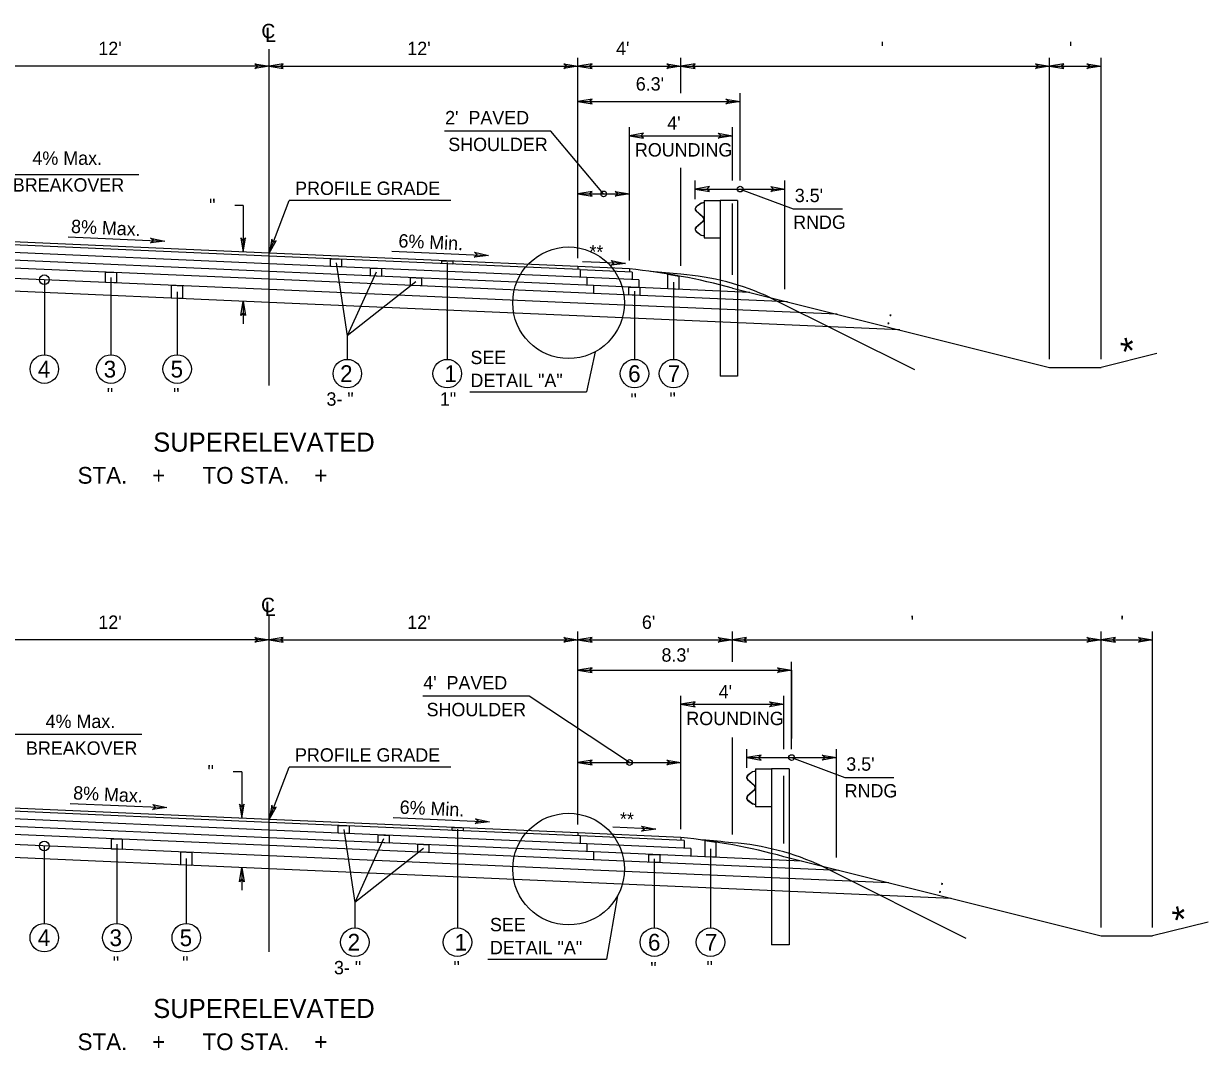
# Model space of a CAD drawing. Extents: x -592 to 1199, y -590 to 416.
# Drawn here: x 1064.4 to 1188.4, y -214.2 to -106.8 of the extents above; entities that cross this region are included whole.
import ezdxf

# ---------------------------------------------------------------- set-up
doc = ezdxf.new("R2010")
doc.units = 0
doc.layers.add('1', color=7, linetype='Continuous')
doc.layers.add('Des_ Drain_ Ftrs', color=7, linetype='Continuous')

msp = doc.modelspace()

# ---------------------------------------------------------------- linework, layer by layer
at = {"layer": '1'}
for p, q in [((1090.11, -144.63), (1090.11, -109.44)), ((1122.44, -131.3), (1122.44, -110.32)), ((1133.21, -114.03), (1133.21, -110.32)), ((1171.8, -141.85), (1171.8, -110.32)), ((1177.19, -141.85), (1177.19, -110.32)), ((1090.11, -111.2), (1057.78, -111.2)), ((1090.11, -111.2), (1122.44, -111.2)), ((1122.44, -111.2), (1133.21, -111.2)), ((1133.21, -111.2), (1171.8, -111.2)), ((1171.8, -111.2), (1177.19, -111.2)), ((1139.41, -123.18), (1139.41, -114.03)), ((1122.44, -114.91), (1139.41, -114.91)), ((1127.83, -131.54), (1127.83, -117.6)), ((1138.6, -123.18), (1138.6, -117.6)), ((1119.6, -117.99), (1108.46, -117.99)), ((1125.13, -124.57), (1119.6, -117.99)), ((1127.83, -118.48), (1138.6, -118.48)), ((1076.5, -122.56), (1062.55, -122.56)), ((1133.21, -132.09), (1133.21, -121.84)), ((1134.72, -125.13), (1134.72, -123.18)), ((1144.1, -134.54), (1144.1, -123.18)), ((1122.44, -124.57), (1127.83, -124.57)), ((1134.72, -124.06), (1144.1, -124.06)), ((1139.41, -124.06), (1144.97, -126.13)), ((1087.41, -125.77), (1086.53, -125.77)), ((1087.41, -125.77), (1087.41, -130.65)), ((1090.11, -130.77), (1092.23, -125.27)), ((1109.15, -125.27), (1092.23, -125.27)), ((1134.78, -126.35), (1135.51, -126.99)), ((1135.32, -125.53), (1134.8, -125.92)), ((1134.8, -126.33), (1135.53, -126.96)), ((1135.33, -125.56), (1134.82, -125.94)), ((1135.63, -125.47), (1135.32, -125.53)), ((1135.63, -125.5), (1135.33, -125.56)), ((1135.63, -125.25), (1135.63, -129.18)), ((1135.63, -125.25), (1137.31, -125.25)), ((1137.31, -125.25), (1137.31, -143.64)), ((1139.14, -125.25), (1137.31, -125.25)), ((1138.6, -133.02), (1138.6, -125.56)), ((1139.14, -125.25), (1139.14, -143.64)), ((1144.97, -126.13), (1150.12, -126.13)), ((1135.51, -127.44), (1134.78, -128.07)), ((1135.53, -127.46), (1134.8, -128.1)), ((1135.6, -127.17), (1135.6, -127.25)), ((1135.63, -127.17), (1135.63, -127.25)), ((1134.8, -128.5), (1135.32, -128.89)), ((1134.82, -128.48), (1135.33, -128.87)), ((1135.32, -128.89), (1135.63, -128.95)), ((1135.33, -128.87), (1135.63, -128.92)), ((1090.11, -131.07), (1057.43, -129.64)), ((1090.11, -130.77), (1057.77, -129.36)), ((1069.09, -129.07), (1079.2, -129.51)), ((1135.63, -129.18), (1137.31, -129.18)), ((1090.11, -132.69), (1055.59, -131.18)), ((1090.11, -131.88), (1056.51, -130.41)), ((1122.44, -132.18), (1090.11, -130.77)), ((1122.68, -132.49), (1090.11, -131.07)), ((1102.96, -130.55), (1113.08, -131)), ((1090.11, -133.5), (1055.59, -131.99)), ((1123.38, -133.33), (1090.11, -131.88)), ((1097.13, -131.78), (1098.3, -139.41)), ((1108.76, -131.74), (1108.76, -141.89)), ((1127.83, -132.42), (1122.44, -132.18)), ((1122.44, -132.18), (1122.44, -132.48)), ((1122.68, -132.49), (1122.68, -133.3)), ((1128.11, -132.75), (1122.68, -132.51)), ((1127.41, -131.86), (1122.91, -131.66)), ((1127.83, -132.42), (1127.83, -132.72)), ((1090.11, -135.92), (1032.91, -133.42)), ((1090.11, -134.57), (1055.59, -133.07)), ((1066.6, -133.55), (1066.6, -141.42)), ((1073.56, -133.31), (1073.56, -141.42)), ((1124.08, -134.17), (1090.11, -132.69)), ((1124.08, -134.98), (1090.11, -133.5)), ((1101.31, -132.76), (1098.3, -139.41)), ((1105.48, -133.78), (1098.3, -139.41)), ((1128.81, -133.57), (1123.38, -133.33)), ((1123.38, -133.33), (1123.38, -134.14)), ((1128.11, -132.75), (1128.11, -133.54)), ((1128.81, -133.57), (1128.81, -134.38)), ((1132.44, -133.81), (1132.44, -141.89)), ((1134.72, -133.19), (1134.72, -133.19)), ((1080.5, -134.82), (1080.5, -141.42)), ((1122.44, -135.99), (1090.11, -134.57)), ((1124.08, -134.17), (1124.08, -134.98)), ((1140.43, -134.88), (1124.08, -134.17)), ((1144.36, -135.86), (1124.08, -134.98)), ((1128.36, -134.76), (1128.36, -141.89)), ((1138.6, -134.43), (1171.8, -142.73)), ((1087.41, -135.8), (1087.41, -138.17)), ((1156.12, -138.8), (1090.11, -135.92)), ((1149.58, -137.17), (1122.44, -135.99)), ((1142.6, -135.43), (1157.65, -142.95)), ((1098.3, -139.41), (1098.3, -141.89)), ((1124.23, -141.1), (1123.35, -145.28)), ((1183.02, -141.27), (1177.19, -142.73)), ((1139.14, -143.64), (1137.31, -143.64)), ((1171.8, -142.73), (1177.19, -142.73)), ((1111.11, -145.28), (1123.35, -145.28)), ((1090.11, -203.88), (1090.11, -168.59)), ((1122.44, -190.55), (1122.44, -170.35)), ((1138.6, -173.51), (1138.6, -170.35)), ((1177.19, -201.33), (1177.19, -170.35)), ((1182.58, -201.33), (1182.58, -170.35)), ((1090.11, -171.23), (1057.78, -171.23)), ((1090.11, -171.23), (1122.44, -171.23)), ((1122.44, -171.23), (1138.6, -171.23)), ((1138.6, -171.23), (1177.19, -171.23)), ((1177.19, -171.23), (1182.58, -171.23)), ((1144.8, -182.67), (1144.8, -173.51)), ((1122.44, -174.39), (1144.8, -174.39)), ((1144.8, -174.39), (1144.8, -181.54)), ((1117.33, -177.12), (1106.19, -177.12)), ((1127.83, -184.06), (1117.33, -177.12)), ((1133.21, -191.02), (1133.21, -177.09)), ((1143.99, -182.67), (1143.99, -177.09)), ((1133.21, -177.97), (1143.99, -177.97)), ((1076.79, -181.14), (1063.31, -181.14)), ((1138.6, -191.58), (1138.6, -181.45)), ((1140.11, -184.62), (1140.11, -182.67)), ((1149.49, -194.01), (1149.49, -182.67)), ((1090.11, -190.02), (1092.21, -184.55)), ((1109.13, -184.55), (1092.21, -184.55)), ((1122.44, -184.06), (1133.21, -184.06)), ((1140.11, -183.55), (1149.49, -183.55)), ((1144.8, -183.55), (1150.36, -185.62)), ((1087.25, -185.02), (1086.37, -185.02)), ((1087.25, -185.02), (1087.25, -189.89)), ((1140.17, -185.84), (1140.9, -186.47)), ((1140.71, -185.02), (1140.19, -185.41)), ((1140.19, -185.82), (1140.92, -186.45)), ((1140.72, -185.05), (1140.21, -185.43)), ((1141.02, -184.96), (1140.71, -185.02)), ((1141.02, -184.99), (1140.72, -185.05)), ((1141.02, -184.73), (1141.02, -188.66)), ((1141.02, -184.73), (1142.71, -184.73)), ((1142.71, -184.73), (1142.71, -203.13)), ((1144.53, -184.73), (1142.71, -184.73)), ((1143.99, -192.55), (1143.99, -185.47)), ((1144.53, -184.73), (1144.53, -203.13)), ((1150.36, -185.62), (1155.51, -185.62)), ((1140.9, -186.92), (1140.17, -187.56)), ((1140.92, -186.95), (1140.19, -187.58)), ((1140.99, -186.66), (1140.99, -186.74)), ((1141.02, -186.66), (1141.02, -186.74)), ((1069.31, -188.34), (1079.43, -188.78)), ((1140.19, -187.99), (1140.71, -188.38)), ((1140.21, -187.97), (1140.72, -188.35)), ((1140.71, -188.38), (1141.02, -188.44)), ((1140.72, -188.35), (1141.02, -188.41)), ((1090.11, -191.13), (1056.51, -189.66)), ((1090.11, -190.32), (1057.43, -188.89)), ((1090.11, -190.02), (1057.77, -188.61)), ((1141.02, -188.66), (1142.71, -188.66)), ((1090.11, -191.94), (1055.59, -190.43)), ((1122.44, -191.43), (1090.11, -190.02)), ((1122.68, -191.74), (1090.11, -190.32)), ((1103.09, -189.81), (1113.2, -190.25)), ((1130.58, -191.04), (1126.09, -190.84)), ((1090.11, -192.75), (1055.6, -191.24)), ((1123.38, -192.58), (1090.11, -191.13)), ((1124.08, -193.42), (1090.11, -191.94)), ((1097.93, -191.07), (1099.09, -198.69)), ((1102.1, -192.05), (1099.09, -198.69)), ((1109.83, -191.04), (1109.83, -201.38)), ((1133.21, -191.9), (1122.44, -191.43)), ((1122.44, -191.43), (1122.44, -191.73)), ((1133.54, -192.22), (1122.68, -191.74)), ((1122.68, -191.74), (1122.68, -192.55)), ((1133.21, -191.9), (1133.21, -192.2)), ((1090.11, -195.17), (1027.93, -192.46)), ((1090.11, -193.83), (1055.59, -192.32)), ((1066.59, -192.8), (1066.59, -200.91)), ((1074.18, -192.59), (1074.18, -200.91)), ((1124.09, -194.23), (1090.11, -192.75)), ((1106.28, -193.06), (1099.09, -198.69)), ((1134.24, -193.06), (1123.38, -192.58)), ((1123.38, -192.58), (1123.38, -193.39)), ((1133.54, -192.22), (1133.54, -193.03)), ((1134.24, -193.06), (1134.24, -193.86)), ((1136.31, -193.09), (1136.31, -201.38)), ((1140.11, -192.68), (1140.11, -192.68)), ((1081.45, -194.12), (1081.45, -200.91)), ((1124.04, -195.31), (1090.11, -193.83)), ((1124.08, -193.42), (1124.08, -194.23)), ((1145.82, -194.37), (1124.08, -193.42)), ((1149.75, -195.35), (1124.08, -194.23)), ((1130.43, -194.13), (1130.43, -201.38)), ((1143.99, -193.91), (1177.19, -202.21)), ((1087.25, -195.05), (1087.25, -197.42)), ((1161.51, -198.29), (1090.11, -195.17)), ((1154.97, -196.66), (1124.04, -195.31)), ((1147.99, -194.91), (1163.04, -202.44)), ((1126.59, -198), (1125.41, -204.64)), ((1099.09, -198.69), (1099.09, -201.38)), ((1188.4, -200.76), (1182.58, -202.21)), ((1144.53, -203.13), (1142.71, -203.13)), ((1177.19, -202.21), (1182.58, -202.21)), ((1113.01, -204.64), (1125.41, -204.64))]:
    msp.add_line(p, q, dxfattribs=at)
for points in [[(1096.56, -131.35), (1097.7, -131.4), (1097.7, -132.21), (1096.56, -132.16)], [(1100.73, -132.34), (1101.88, -132.39), (1101.88, -133.2), (1100.73, -133.15)], [(1108.18, -131.56), (1109.33, -131.61), (1109.33, -131.91), (1108.18, -131.86)], [(1072.99, -132.75), (1074.14, -132.8), (1074.14, -133.88), (1072.99, -133.83)], [(1104.91, -133.33), (1106.06, -133.38), (1106.06, -134.19), (1104.91, -134.14)], [(1131.86, -132.96), (1133.01, -133.16), (1133.01, -134.56), (1131.86, -134.51)], [(1079.92, -134.13), (1081.07, -134.18), (1081.07, -135.53), (1079.92, -135.48)], [(1127.78, -134.33), (1128.93, -134.38), (1128.93, -135.19), (1127.78, -135.14)], [(1097.35, -190.64), (1098.5, -190.69), (1098.5, -191.5), (1097.35, -191.45)], [(1109.26, -190.86), (1110.41, -190.91), (1110.41, -191.21), (1109.26, -191.16)], [(1073.61, -192.03), (1074.75, -192.08), (1074.75, -193.16), (1073.61, -193.11)], [(1101.53, -191.63), (1102.68, -191.68), (1102.68, -192.49), (1101.53, -192.44)], [(1105.7, -192.62), (1106.85, -192.67), (1106.85, -193.48), (1105.7, -193.43)], [(1135.74, -192.21), (1136.88, -192.38), (1136.88, -193.98), (1135.74, -193.93)], [(1080.88, -193.42), (1082.02, -193.47), (1082.02, -194.82), (1080.88, -194.77)], [(1129.86, -193.67), (1131.01, -193.72), (1131.01, -194.53), (1129.86, -194.48)]]:
    msp.add_lwpolyline(points, close=True, dxfattribs=at)
for centre, radius in [((1139.41, -124.06), 0.3), ((1125.13, -124.57), 0.3), ((1121.46, -135.96), 5.84), ((1066.6, -133.55), 0.5), ((1066.6, -142.9), 1.49), ((1073.56, -142.9), 1.49), ((1080.5, -142.9), 1.49), ((1098.3, -143.37), 1.49), ((1108.76, -143.37), 1.49), ((1128.36, -143.37), 1.49), ((1132.44, -143.37), 1.49), ((1144.8, -183.55), 0.3), ((1127.83, -184.06), 0.3), ((1121.46, -195.21), 5.84), ((1066.59, -192.8), 0.5), ((1066.59, -202.39), 1.49), ((1074.18, -202.39), 1.49), ((1081.45, -202.39), 1.49), ((1099.09, -202.86), 1.49), ((1109.83, -202.86), 1.49), ((1130.43, -202.86), 1.49), ((1136.31, -202.86), 1.49)]:
    msp.add_circle(centre, radius, dxfattribs=at)
for centre, radius, start, end in [((1134.97, -126.14), 0.278, 126.9799, 229.021), ((1134.97, -126.14), 0.249, 126.9799, 229.021), ((1135.35, -127.17), 0.249, 0, 49.0365), ((1135.35, -127.25), 0.249, 310.9635, 0), ((1135.35, -127.17), 0.278, 0, 49.0365), ((1135.35, -127.25), 0.278, 310.9635, 0), ((1134.97, -128.28), 0.278, 130.979, 233.0201), ((1134.97, -128.28), 0.249, 130.979, 233.0201), ((1120.94, -199.25), 67.19, 74.7593, 84.1179), ((1122.39, -233.64), 101.24, 83.8633, 85.6775), ((1131.09, -160.26), 27.37, 65.1374, 85.5513), ((1140.36, -185.63), 0.278, 126.9799, 229.021), ((1140.36, -185.63), 0.249, 126.9799, 229.021), ((1140.74, -186.66), 0.249, 0, 49.0365), ((1140.74, -186.74), 0.249, 310.9635, 0), ((1140.74, -186.66), 0.278, 0, 49.0365), ((1140.74, -186.74), 0.278, 310.9635, 0), ((1140.36, -187.77), 0.278, 130.979, 233.0201), ((1140.36, -187.77), 0.249, 130.979, 233.0201), ((1126.33, -258.74), 67.19, 74.7602, 84.1188), ((1127.78, -293.12), 101.24, 83.8633, 85.6775), ((1136.48, -219.74), 27.37, 65.1374, 85.5513)]:
    msp.add_arc(centre, radius, start, end, dxfattribs=at)
at = {"layer": 'Des_ Drain_ Ftrs'}
for points in [[(1090.11, -111.2), (1088.62, -111.45), (1088.91, -111.2), (1088.62, -110.96)], [(1090.11, -111.2), (1091.6, -111.45), (1091.3, -111.2), (1091.6, -110.96)], [(1122.44, -111.2), (1120.95, -111.45), (1121.24, -111.2), (1120.95, -110.96)], [(1122.44, -111.2), (1123.93, -111.45), (1123.63, -111.2), (1123.93, -110.96)], [(1133.21, -111.2), (1131.73, -111.45), (1132.02, -111.2), (1131.73, -110.96)], [(1133.21, -111.2), (1134.7, -111.45), (1134.41, -111.2), (1134.7, -110.96)], [(1171.8, -111.2), (1170.31, -111.45), (1170.61, -111.2), (1170.31, -110.96)], [(1171.8, -111.2), (1173.29, -111.45), (1172.99, -111.2), (1173.29, -110.96)], [(1177.19, -111.2), (1175.7, -111.45), (1176, -111.2), (1175.7, -110.96)], [(1122.44, -114.91), (1123.92, -115.15), (1123.63, -114.91), (1123.92, -114.66)], [(1139.41, -114.91), (1137.92, -115.15), (1138.22, -114.91), (1137.92, -114.66)], [(1127.83, -118.48), (1129.31, -118.73), (1129.02, -118.48), (1129.31, -118.23)], [(1138.6, -118.48), (1137.11, -118.73), (1137.41, -118.48), (1137.11, -118.23)], [(1134.72, -124.06), (1136.21, -124.31), (1135.91, -124.06), (1136.21, -123.81)], [(1144.1, -124.06), (1142.61, -124.31), (1142.91, -124.06), (1142.61, -123.81)], [(1122.44, -124.57), (1123.93, -124.82), (1123.63, -124.57), (1123.93, -124.32)], [(1127.83, -124.57), (1126.34, -124.82), (1126.63, -124.57), (1126.34, -124.32)], [(1079.2, -129.51), (1077.7, -129.69), (1078.01, -129.46), (1077.72, -129.2)], [(1087.41, -130.65), (1087.66, -129.16), (1087.41, -129.46), (1087.17, -129.16)], [(1090.11, -130.77), (1090.87, -129.47), (1090.53, -129.65), (1090.41, -129.29)], [(1113.08, -131), (1111.58, -131.18), (1111.88, -130.94), (1111.6, -130.68)], [(1127.41, -131.86), (1125.91, -132.04), (1126.21, -131.81), (1125.93, -131.55)], [(1087.41, -135.8), (1087.66, -137.29), (1087.41, -137), (1087.17, -137.29)], [(1090.11, -171.23), (1088.62, -171.48), (1088.91, -171.23), (1088.62, -170.98)], [(1090.11, -171.23), (1091.6, -171.48), (1091.3, -171.23), (1091.6, -170.98)], [(1122.44, -171.23), (1120.95, -171.48), (1121.24, -171.23), (1120.95, -170.98)], [(1122.44, -171.23), (1123.93, -171.48), (1123.63, -171.23), (1123.93, -170.98)], [(1138.6, -171.23), (1137.11, -171.48), (1137.41, -171.23), (1137.11, -170.98)], [(1138.6, -171.23), (1140.09, -171.48), (1139.79, -171.23), (1140.09, -170.98)], [(1177.19, -171.23), (1175.7, -171.48), (1176, -171.23), (1175.7, -170.98)], [(1177.19, -171.23), (1178.68, -171.48), (1178.38, -171.23), (1178.68, -170.98)], [(1182.58, -171.23), (1181.09, -171.48), (1181.38, -171.23), (1181.09, -170.98)], [(1122.44, -174.39), (1123.93, -174.64), (1123.63, -174.39), (1123.93, -174.14)], [(1144.8, -174.39), (1143.31, -174.64), (1143.61, -174.39), (1143.31, -174.14)], [(1133.21, -177.97), (1134.7, -178.22), (1134.41, -177.97), (1134.7, -177.72)], [(1143.99, -177.97), (1142.5, -178.22), (1142.8, -177.97), (1142.5, -177.72)], [(1140.11, -183.55), (1141.6, -183.8), (1141.3, -183.55), (1141.6, -183.3)], [(1149.49, -183.55), (1148, -183.8), (1148.3, -183.55), (1148, -183.3)], [(1122.44, -184.06), (1123.93, -184.3), (1123.63, -184.06), (1123.93, -183.81)], [(1133.21, -184.06), (1131.73, -184.3), (1132.02, -184.06), (1131.73, -183.81)], [(1087.25, -189.89), (1087.5, -188.41), (1087.25, -188.7), (1087.01, -188.41)], [(1079.43, -188.78), (1077.93, -188.96), (1078.23, -188.73), (1077.95, -188.47)], [(1090.11, -190.02), (1090.87, -188.72), (1090.53, -188.9), (1090.41, -188.54)], [(1113.2, -190.25), (1111.7, -190.43), (1112.01, -190.2), (1111.73, -189.94)], [(1130.58, -191.04), (1129.08, -191.23), (1129.39, -190.99), (1129.1, -190.73)], [(1087.25, -195.05), (1087.5, -196.54), (1087.25, -196.24), (1087.01, -196.54)]]:
    msp.add_lwpolyline(points, close=True, dxfattribs=at)

# ---------------------------------------------------------------- texts
at = {"layer": '1'}
for s, height, p in [("12'", 1.4, (1072.25, -110.05)), ("12'", 1.4, (1104.58, -110.05)), ("4'", 1.4, (1126.43, -110.05)), ("  '", 1.4, (1153.07, -110.05)), (" '", 1.4, (1173.3, -110.05)), ("6.3'", 1.4, (1128.49, -113.76)), ("2'  PAVED", 1.4, (1108.54, -117.29)), ("4'", 1.4, (1131.78, -117.86)), ('SHOULDER', 1.4, (1108.87, -120.09)), ('4% Max.', 1.4, (1065.35, -121.53)), ('ROUNDING', 1.4, (1128.4, -120.66)), ('BREAKOVER', 1.4, (1063.3, -124.33)), ('PROFILE GRADE', 1.4, (1092.84, -124.68)), ("3.5'", 1.4, (1145.13, -125.43)), ('RNDG', 1.4, (1144.96, -128.23)), ('SEE', 1.4, (1111.19, -142.38)), ('4', 1.75, (1065.92, -143.78)), ('3', 1.75, (1072.81, -143.78)), ('5', 1.75, (1079.81, -143.78)), ('2', 1.75, (1097.55, -144.25)), ('1', 1.75, (1108.46, -144.25)), ('6', 1.75, (1127.69, -144.25)), ('7', 1.75, (1131.84, -144.25)), ('DETAIL "A"', 1.4, (1111.19, -144.78)), (' "', 1.4, (1072.62, -146.26)), (' "', 1.4, (1079.55, -146.26)), ('3- "', 1.4, (1096.12, -146.73)), ('1"', 1.4, (1107.99, -146.73)), (' "', 1.4, (1127.41, -146.83)), (' "', 1.4, (1131.49, -146.73)), ('SUPERELEVATED', 2, (1077.99, -151.54)), ('STA.    +      TO STA.    +     ', 1.75, (1070.08, -154.89)), ("12'", 1.4, (1072.25, -170.08)), ("12'", 1.4, (1104.58, -170.08)), ("6'", 1.4, (1129.13, -170.08)), ("  '", 1.4, (1156.2, -170.08)), (" '", 1.4, (1178.69, -170.08)), ("8.3'", 1.4, (1131.18, -173.51)), ("4'  PAVED", 1.4, (1106.25, -176.42)), ("4'", 1.4, (1137.17, -177.35)), ('SHOULDER', 1.4, (1106.6, -179.22)), ('4% Max.', 1.4, (1066.73, -180.45)), ('ROUNDING', 1.4, (1133.78, -180.15)), ('BREAKOVER', 1.4, (1064.68, -183.25)), ('PROFILE GRADE', 1.4, (1092.83, -183.97)), ("3.5'", 1.4, (1150.52, -184.92)), ('RNDG', 1.4, (1150.35, -187.72)), ('SEE', 1.4, (1113.23, -201.72)), ('4', 1.75, (1065.91, -203.27)), ('3', 1.75, (1073.42, -203.27)), ('5', 1.75, (1080.76, -203.27)), ('2', 1.75, (1098.34, -203.74)), ('1', 1.75, (1109.53, -203.74)), ('6', 1.75, (1129.77, -203.74)), ('7', 1.75, (1135.72, -203.74)), ('DETAIL "A"', 1.4, (1113.23, -204.12)), (' "', 1.4, (1073.24, -205.75)), (' "', 1.4, (1080.5, -205.75)), ('3- "', 1.4, (1096.91, -206.22)), (' "', 1.4, (1108.89, -206.22)), (' "', 1.4, (1129.49, -206.32)), (' "', 1.4, (1135.37, -206.22)), ('SUPERELEVATED', 2, (1077.99, -210.79)), ('STA.    +      TO STA.    +     ', 1.75, (1070.08, -214.15))]:
    msp.add_text(s, height=height, dxfattribs=at).set_placement(p)
for s, height, rotation, p in [('  "', 1.4, 0.1438, (1082.8, -126.48)), ('8% Max.', 1.4, 357.3763, (1069.37, -128.65)), ('6% Min.', 1.4, 357.373, (1103.63, -130.16)), ('**', 1.4, 357.2161, (1123.59, -131.3)), (' : ', 1.4, 345.7718, (1154.15, -138.02)), ('*', 2.8, 12.8479, (1179.65, -142.53)), ('  "', 1.4, 0.1438, (1082.64, -185.72)), ('8% Max.', 1.4, 357.3764, (1069.59, -187.92)), ('6% Min.', 1.4, 357.3728, (1103.76, -189.41)), ('**', 1.4, 357.2167, (1126.79, -190.64)), (' : ', 1.4, 345.7718, (1159.54, -197.51)), ('*', 2.8, 12.8479, (1185.04, -202.02))]:
    msp.add_text(s, height=height, rotation=rotation, dxfattribs=at).set_placement(p)
at = {"layer": 'Des_ Drain_ Ftrs'}
for s, p in [('C', (1089.31, -108.28)), ('L', (1089.71, -108.68)), ('C', (1089.28, -168.32)), ('L', (1089.68, -168.72))]:
    msp.add_text(s, height=1.5, dxfattribs=at).set_placement(p)

doc.saveas('drawing.dxf')
